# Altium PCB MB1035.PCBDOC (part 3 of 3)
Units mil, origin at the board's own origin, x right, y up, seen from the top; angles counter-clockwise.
Board outline 2598.43 x 3818.9 mil, 2 copper layers (TOP, Bottom); 145 components, 171 nets, 593 pads, 200 vias.
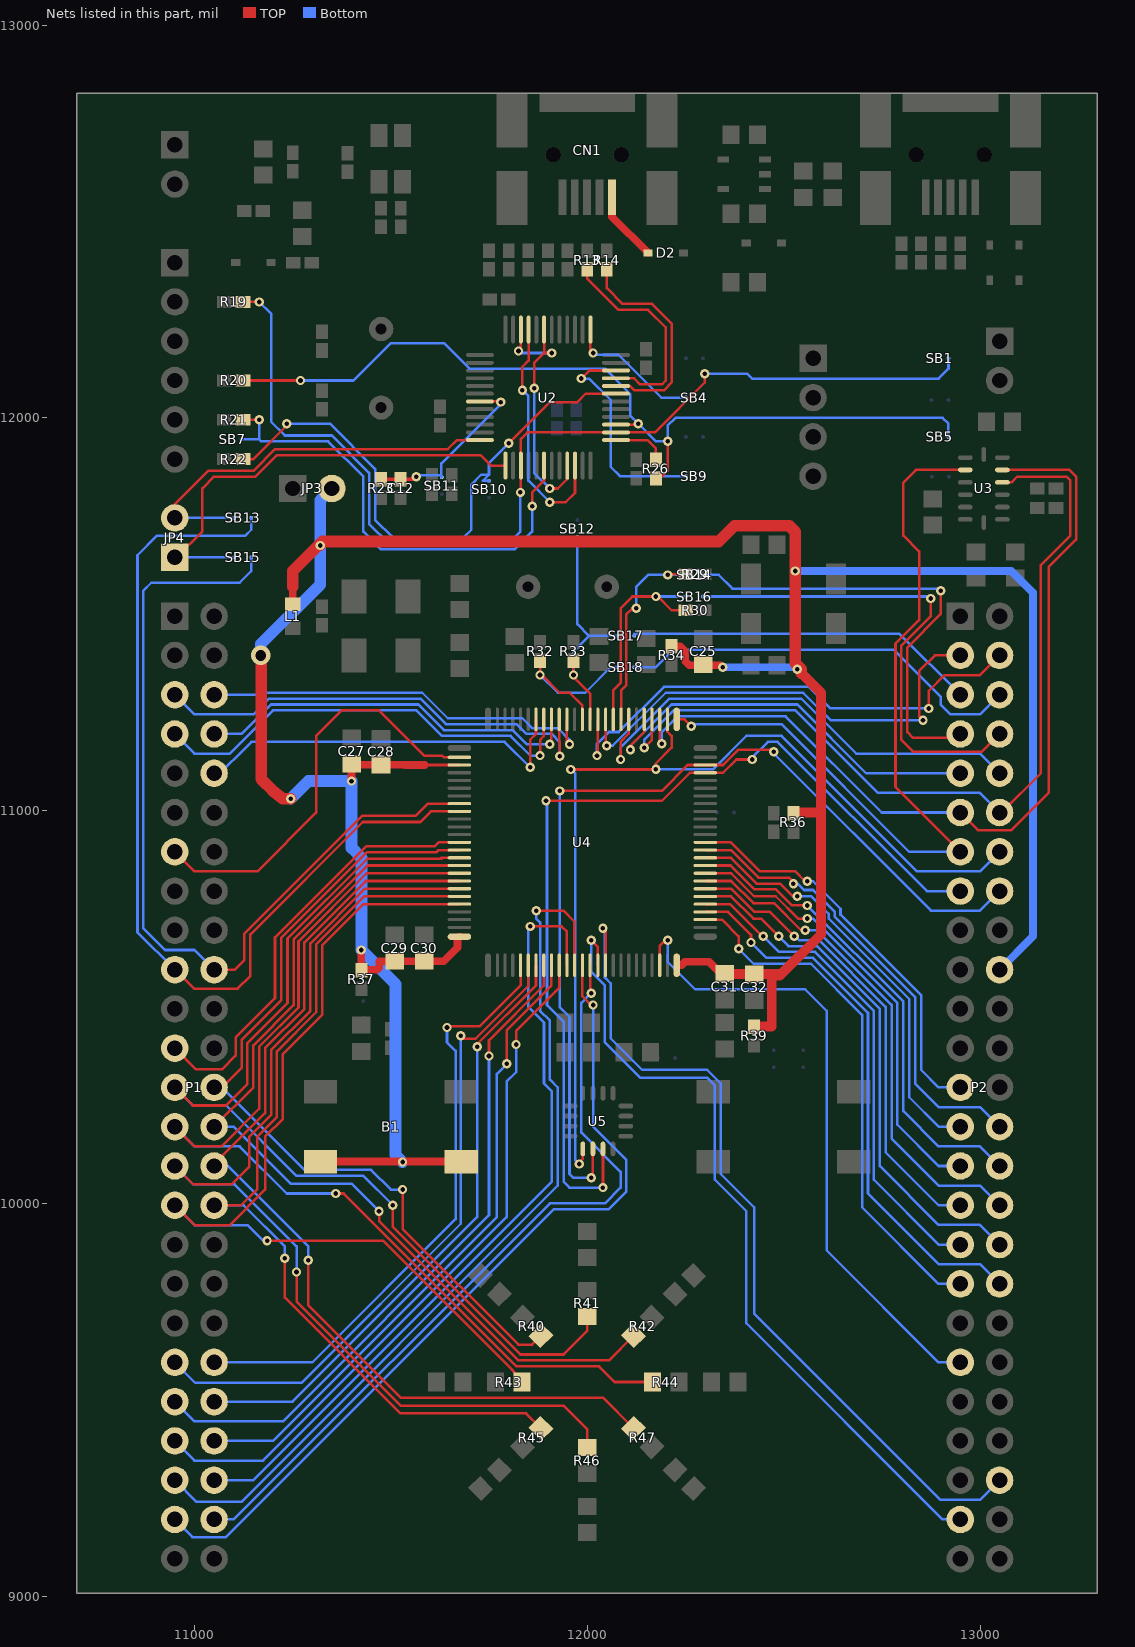
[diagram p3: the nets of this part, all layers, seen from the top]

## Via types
v1: diameter 23.62, hole 11.81, TOP to Bottom, 199 vias
v2: diameter 50, hole 27.56, TOP to Bottom, 1 vias

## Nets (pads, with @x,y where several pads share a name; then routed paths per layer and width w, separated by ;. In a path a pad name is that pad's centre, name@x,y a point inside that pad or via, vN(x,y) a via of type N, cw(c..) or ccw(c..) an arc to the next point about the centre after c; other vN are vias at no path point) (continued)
PC0: P1.6 U4.15 | length 1037.5
  TOP w6.5: U4.15@11947.32,11232.02 11947.32,11168.94 v1(11953.93,11168.94)
  Bottom w6.5: P1.6@11048.93,11294.92 11178.93,11294.92 11183.93,11299.92 11578.93,11299.92 11643.93,11234.92 11833.93,11234.92 11858.93,11209.92 11923.93,11209.92 11953.93,11179.92 v1(11953.93,11168.94)
PC1: P1.5 U4.16 | length 1194.5
  TOP w6.5: U4.16@11927.63,11232.02 11927.63,11176.22 11928.93,11174.92 v1(11928.93,11137.92)
  Bottom w6.5: P1.5@10948.93,11294.92 10998.93,11244.92 11148.93,11244.92 11188.93,11284.92 11573.93,11284.92 11638.93,11219.92 11818.93,11219.92 11843.93,11194.92 11908.93,11194.92 11928.93,11174.92 v1(11928.93,11137.92)
PC2: P1.8 U4.17 | length 1055.2
  TOP w6.5: U4.17@11906.95,11228.47 11906.95,11168.94 v1(11903.93,11168.94) 11907.95,11172.96 U4.17@11907.95,11232.02
  Bottom w6.5: P1.8@11048.93,11194.92 11118.93,11194.92 11193.93,11269.92 11568.93,11269.92 11633.93,11204.92 11808.93,11204.92 11844.92,11168.94 v1(11903.93,11168.94)
PC3: P1.7 U4.18 | length 1139.9
  TOP w6.5: v1(11878.93,11139.92) 11878.93,11179.92 11888.26,11189.25 U4.18@11888.26,11232.02
  Bottom w6.5: P1.7@10948.93,11194.92 10998.93,11144.92 11088.93,11144.92 11198.93,11254.92 11563.93,11254.92 11628.93,11189.92 11803.93,11189.92 11853.93,11139.92 v1(11878.93,11139.92)
PC4: P1.20 SB15.1 U4.33 | length 2253.5
  TOP w6.5: P1.20@11048.93,10594.92 11101.75,10594.93 11125.36,10618.54 11125.36,10686.18 11425.67,10986.48 11562.28,10986.48 11593.25,11017.45 U4.33@11673.69,11017.45
  Bottom w6.5: P1.20@11048.93,10594.92 10998.93,10644.92 10923.93,10644.92 10868.93,10699.92 10868.93,11559.92 10888.93,11579.92 11113.93,11579.92 11143.62,11609.61 SB15.1@11143.62,11644.92
PC5: P1.19 SB13.1 U4.34 | length 2434.6
  TOP w6.5: P1.19@10948.93,10594.92 10998.1,10546.42 11108.93,10546.42 11141.1,10578.59 11141.1,10684.37 11427.47,10970.74 11573.95,10970.74 11601.03,10997.81 11601.07,10997.77 U4.34@11673.69,10997.77
  Bottom w6.5: P1.19@10948.93,10594.92 10853.93,10689.92 10853.93,11649.92 10903.93,11699.92 11128.62,11699.92 11143.62,11714.92 SB13.1@11143.62,11744.92
PC6: P1.47 U4.63 | length 2158.7
  TOP w6.5: U4.63@11986.69,10606.03 11986.69,10527.17 12008.93,10504.92 v1(12013.93,10504.92)
  Bottom w6.5: P1.47@10948.93,9194.92 10993.93,9149.92 11078.93,9149.92 11913.93,9984.92 12053.93,9984.92 12098.93,10029.92 12098.93,10109.92 12013.93,10194.92 v1(12013.93,10504.92)
PC7: P1.48 U4.64 | length 2005.5
  TOP w6.5: U4.64@12006.37,10606.03 12006.37,10534.92 v1(12008.93,10534.92)
  Bottom w6.5: P1.48@11048.93,9194.92 11098.93,9194.92 11903.93,9999.92 12043.93,9999.92 12083.93,10039.92 12083.93,10079.92 11983.93,10179.92 11983.93,10509.92 v1(12008.93,10534.92)
PC8: P2.47 U4.65 | length 2061.3
  TOP w6.5: v1(12008.93,10669.92) 12026.06,10652.8 U4.65@12026.06,10606.03
  Bottom w6.5: v1(12008.93,10669.92) 12008.93,10589.92 12043.93,10554.92 12043.93,10409.92 12133.93,10319.92 12303.93,10319.92 12323.93,10299.92 12323.93,10059.92 12403.93,9979.92 12403.93,9694.92 12903.93,9194.92 P2.47@12948.93,9194.92
PC9: P2.46 U4.66 | length 2179.3
  TOP w6.5: v1(12038.93,10699.92) 12045.74,10699.92 U4.66@12045.74,10606.03
  Bottom w6.5: v1(12038.93,10699.92) 12043.93,10694.92 12043.93,10574.92 12058.93,10559.92 12058.93,10419.92 12138.93,10339.92 12303.93,10339.92 12338.93,10304.92 12338.93,10074.92 12423.93,9989.92 12423.93,9719.92 12898.93,9244.92 12998.93,9244.92 P2.46@13048.93,9294.92
PC10: P2.35 U4.78 | length 1338.7
  TOP w6.5: U4.78@12299.68,10722.18 12341.68,10722.18 12384.56,10679.29 v1(12384.56,10648.07)
  Bottom w6.5: v1(12384.56,10648.07) 12422.71,10609.92 12568.93,10609.92 12698.93,10479.92 12698.93,9989.92 12893.93,9794.92 P2.35@12948.93,9794.92
PC11: P2.36 U4.79 | length 1422.3
  TOP w6.5: U4.79@12299.68,10741.86 12357.4,10741.86 12416.04,10683.22 v1(12416.04,10663.81)
  Bottom w6.5: v1(12416.04,10663.81) 12454.93,10624.92 12573.93,10624.92 12713.93,10484.92 12713.93,10024.92 12893.93,9844.92 12998.93,9844.92 P2.36@13048.93,9794.92
PC12: P2.33 U4.80 | length 1273.2
  TOP w6.5: U4.80@12299.68,10761.55 12362.31,10761.55 12448.93,10674.92 12452.15,10674.92 v1(12447.52,10679.55)
  Bottom w6.5: v1(12447.52,10679.55) 12487.15,10639.92 12578.93,10639.92 12728.93,10489.92 12728.93,10059.92 12893.93,9894.92 P2.33@12948.93,9894.92
PC13: P2.10 U4.7 | length 1236.2
  TOP w6.5: v1(12083.93,11129.92) 12083.93,11174.92 12104.8,11195.79 U4.7@12104.8,11232.02
  Bottom w6.5: v1(12083.93,11129.92) 12083.93,11159.92 12208.93,11284.92 12543.93,11284.92 12683.93,11144.92 12998.93,11144.92 P2.10@13048.93,11094.92
PC14: P2.7 SB14.1 | length 1168.3
  TOP w6.5: v1(12898.93,11559.92) 12898.93,11499.92 12813.93,11414.92 12813.93,11199.92 12828.93,11184.92 12948.93,11184.92 P2.7@12948.93,11194.92
  Bottom w6.5: SB14.1@12293.62,11599.92 12333.93,11599.92 12368.93,11564.92 12893.93,11564.92 v1(12898.93,11559.92)
PC14-OSC32_IN: R29.1 SB14.2 U4.8 | length 546.5
  TOP w6.5: U4.8@12085.11,11232.02 12085.11,11306.1 12098.93,11319.92 12098.93,11499.92 12113.93,11514.92 v1(12123.93,11514.92) ; v1(12203.93,11599.92) 12203.93,11601.42 R29.1@12250.31,11601.42
  Bottom w6.5: v1(12123.93,11514.92) 12123.93,11569.92 12153.93,11599.92 v1(12203.93,11599.92) SB14.2@12250.31,11599.92
PC15: P2.8 SB16.1 | length 1254.5
  TOP w6.5: v1(12873.93,11539.92) 12873.93,11494.92 12798.93,11419.92 12798.93,11179.92 12828.93,11149.92 13003.93,11149.92 P2.8@13048.93,11194.92
  Bottom w6.5: SB16.1@12293.62,11544.92 12863.93,11544.92 12868.93,11539.92 v1(12873.93,11539.92)
PC15-OSC32_OUT: R30.1 SB16.2 U4.9 | length 560.3
  TOP w6.5: U4.9@12065.43,11232.02 12065.43,11306.42 12083.93,11324.92 12083.93,11514.92 12113.93,11544.92 v1(12173.93,11544.92) 12178.93,11544.92 12213.93,11509.92 R30.1@12250.31,11509.92
  Bottom w6.5: v1(12173.93,11544.92) SB16.2@12250.31,11544.92
PD0: P2.34 U4.81 | length 1350.7
  TOP w6.5: U4.81@12299.68,10781.23 12365.27,10781.23 12421.82,10724.68 12441.75,10724.68 v1(12486.87,10679.55)
  Bottom w6.5: v1(12486.87,10679.55) 12511.5,10654.92 12583.93,10654.92 12743.93,10494.92 12743.93,10094.92 12893.93,9944.92 12998.93,9944.92 P2.34@13048.93,9894.92
PD1: P2.31 U4.82 | length 1199.8
  TOP w6.5: U4.82@12299.68,10800.92 12365.27,10800.92 12423.79,10742.39 12463.38,10742.39 v1(12526.22,10679.55)
  Bottom w6.5: v1(12526.22,10679.55) 12528.93,10679.55 12538.56,10669.92 12588.93,10669.92 12758.93,10499.92 12758.93,10129.92 12893.93,9994.92 P2.31@12948.93,9994.92
PD2: P2.32 U4.83 | length 1290.4
  TOP w6.5: U4.83@12299.68,10820.6 12365.27,10820.6 12421.83,10764.04 12474.82,10764.04 12543.93,10694.92 v1(12553.93,10694.92)
  Bottom w6.5: v1(12553.93,10694.92) 12583.93,10694.92 12773.93,10504.92 12773.93,10164.92 12893.93,10044.92 12998.93,10044.92 P2.32@13048.93,9994.92
PD3: P2.29 U4.84 | length 1139.6
  TOP w6.5: U4.84@12299.68,10840.29 12365.27,10840.29 12423.8,10781.75 12479,10781.75 12535.83,10724.92 v1(12558.93,10724.92)
  Bottom w6.5: v1(12558.93,10724.92) 12573.93,10724.92 12788.93,10509.92 12788.93,10199.92 12893.93,10094.92 P2.29@12948.93,10094.92
PD4: P2.30 U4.85 | length 1229.2
  TOP w6.5: U4.85@12299.68,10859.97 12363.89,10859.97 12423.93,10799.92 12478.93,10799.92 12520.6,10758.25 v1(12558.93,10758.25)
  Bottom w6.5: v1(12558.93,10758.25) 12803.93,10513.25 12803.93,10234.92 12893.93,10144.92 12998.93,10144.92 P2.30@13048.93,10094.92
PD5: P2.27 U4.86 | length 1086.3
  TOP w6.5: U4.86@12299.68,10879.66 12365.27,10879.66 12431.68,10813.24 12490.61,10813.24 12521.99,10781.86 v1(12534.09,10781.86)
  Bottom w6.5: v1(12534.09,10781.86) 12568.93,10781.86 12613.93,10736.86 12613.93,10724.92 12818.93,10519.92 12818.93,10269.92 12893.93,10194.92 P2.27@12948.93,10194.92
PD6: P2.28 U4.87 | length 1187.3
  TOP w6.5: U4.87@12299.68,10899.34 12364.52,10899.34 12434.77,10829.08 12513.19,10829.08 12528.93,10813.34 v1(12523.93,10813.34)
  Bottom w6.5: v1(12523.93,10813.34) 12535.51,10813.34 12551.25,10797.6 12573.93,10797.6 12628.93,10742.6 12628.93,10729.92 12833.93,10524.92 12833.93,10304.92 12893.93,10244.92 12998.93,10244.92 P2.28@13048.93,10194.92
PD7: P2.25 U4.88 | length 1027.9
  TOP w6.5: U4.88@12299.68,10919.03 12364.83,10919.03 12438.93,10844.92 12528.93,10844.92 12553.93,10819.92 v1(12558.93,10819.92)
  Bottom w6.5: v1(12558.93,10819.92) 12573.93,10819.92 12643.93,10749.92 12643.93,10734.92 12848.93,10529.92 12848.93,10339.92 12893.93,10294.92 P2.25@12948.93,10294.92
PD8: P1.40 U4.55 | length 1545.9
  TOP w6.5: v1(11641.93,10447.42) 11644.93,10450.42 11725,10450.42 11829.21,10554.63 U4.55@11829.21,10606.03
  Bottom w6.5: P1.40@11048.93,9594.92 11053.93,9594.92 11298.93,9594.92 11663.93,9959.92 11663.93,10387.92 11641.93,10409.92 v1(11641.93,10447.42)
PD9: P1.39 U4.56 | length 1678.9
  TOP w6.5: v1(11676.93,10426.42) 11683.93,10419.42 11715.19,10419.42 11848.89,10553.12 U4.56@11848.89,10606.03
  Bottom w6.5: P1.39@10948.93,9594.92 11000.93,9542.93 11271.94,9542.93 11676.93,9947.92 v1(11676.93,10426.42)
PD10: P1.42 U4.57 | length 1567.8
  TOP w6.5: v1(11718.93,10398.42) 11718.93,10404.92 11868.58,10554.57 U4.57@11868.58,10606.03
  Bottom w6.5: P1.42@11048.93,9494.92 11248.93,9494.92 11718.93,9964.92 v1(11718.93,10398.42)
PD11: P1.41 U4.58 | length 1732
  TOP w6.5: v1(11748.93,10374.92) 11748.93,10414.92 11888.26,10554.25 U4.58@11888.26,10606.03
  Bottom w6.5: P1.41@10948.93,9494.92 10998.93,9444.92 11223.93,9444.92 11748.93,9969.92 v1(11748.93,10374.92)
PD12: P1.44 U4.59 | length 1655.1
  TOP w6.5: v1(11794.31,10354.92) 11793.93,10355.3 11793.93,10439.92 11907.95,10553.94 U4.59@11907.95,10606.03
  Bottom w6.5: P1.44@11048.93,9394.92 11198.93,9394.92 11768.93,9964.92 11768.93,10329.54 v1(11794.31,10354.92)
PD13: P1.43 U4.60 | length 1819
  TOP w6.5: v1(11817.92,10404.1) 11817.92,10438.91 11927.63,10548.62 U4.60@11927.63,10606.03
  Bottom w6.5: P1.43@10948.93,9394.92 10998.93,9344.92 11173.93,9344.92 11793.93,9964.92 11793.93,10309.67 11817.92,10333.66 v1(11817.92,10404.1)
PD14: P1.46 U4.61 | length 2039.1
  TOP w6.5: v1(11853.93,10704.92) 11933.93,10704.92 11947.32,10691.54 U4.61@11947.32,10606.03
  Bottom w6.5: P1.46@11048.93,9294.92 11148.93,9294.92 11908.93,10054.92 11908.93,10284.92 11888.93,10304.92 11888.93,10459.92 11848.93,10499.92 11848.93,10704.92 v1(11853.93,10704.92)
PD15: P1.45 U4.62 | length 2275.1
  TOP w6.5: v1(11868.93,10744.92) 11938.93,10744.92 11966,10717.86 11966,10606.03 U4.62@11967,10606.03
  Bottom w6.5: P1.45@10948.93,9294.92 11003.93,9239.92 11118.93,9239.92 11923.93,10044.92 11923.93,10294.92 11903.93,10314.92 11903.93,10464.92 11878.93,10489.92 11878.93,10714.92 11868.93,10724.92 v1(11868.93,10744.92)
PE0: P2.15 U4.97 U5.7 | length 2472.6
  TOP w6.5: v1(11893.93,11024.92) 12188.93,11024.92 12260.2,11096.19 U4.97@12299.68,11096.19 12345.2,11096.19 12378.93,11129.92 v1(12418.93,11129.92) ; v1(12038.93,10039.92) 12039.14,10039.92 U5.7@12039.14,10138.41
  Bottom w6.5: v1(11893.93,11024.92) 11896.62,11024.92 11896.62,10504.73 11938.93,10462.42 11938.93,10054.92 11953.93,10039.92 v1(12038.93,10039.92) ; v1(12418.93,11129.92) 12418.93,11134.92 12458.93,11174.92 12483.93,11174.92 12863.93,10794.92 P2.15@12948.93,10794.92
PE1: P2.16 U4.98 U5.6 | length 2482.5
  TOP w6.5: v1(11928.93,11049.92) 12188.93,11049.92 12254.89,11115.88 U4.98@12299.68,11115.88 12344.89,11115.88 12383.93,11154.92 12473.93,11154.92 v1(12473.93,11149.92) ; v1(12008.93,10064.92) 12013.55,10064.92 U5.6@12013.55,10138.41
  Bottom w6.5: v1(11928.93,11049.92) 11928.93,10499.92 11953.93,10474.92 11953.93,10074.92 11963.93,10064.92 v1(12008.93,10064.92) ; v1(12473.93,11149.92) 12473.93,11144.92 12873.93,10744.92 12998.93,10744.92 P2.16@13048.93,10794.92
PE2: P2.13 U3.9 U4.1 | length 2096.7
  TOP w6.5: U4.1@12226.84,11232.02 12246.84,11232.02 v1(12263.93,11214.92) ; P2.13@12948.93,10894.92 12783.93,11059.92 12783.93,11424.92 12843.93,11484.92 12843.93,11659.92 12803.93,11699.92 12803.93,11834.92 12836.18,11867.17 U3.9@12961.69,11867.17
  Bottom w6.5: v1(12263.93,11214.92) 12258.93,11219.92 12493.93,11219.92 12818.93,10894.92 P2.13@12948.93,10894.92
PE3: P2.14 U4.2 U5.5 | length 2504.1
  TOP w6.5: v1(11956.93,11104.42) v1@12173.43,11104.42 ; v1(11978.93,10099.92) 11973.93,10099.92 11987.96,10113.95 U5.5@11987.96,10138.41 ; v1(12173.93,11104.92) v1@12173.43,11104.42 ; U4.2@12203.22,11232.02 12203.22,11200.63 12213.93,11189.92 12213.93,11159.92 12173.43,11119.42 v1@12173.43,11104.42
  Bottom w6.5: v1(11956.93,11104.42) 11959.19,11104.42 11968.93,11094.68 11968.93,10109.92 v1(11978.93,10099.92) ; v1(12173.93,11104.92) 12318.93,11104.92 12403.93,11189.92 12493.93,11189.92 12838.93,10844.92 12998.93,10844.92 P2.14@13048.93,10894.92
PE4: P2.11 U3.5 U4.3 | length 2287.4
  TOP w6.5: U4.3@12183.54,11232.02 12183.54,11169.92 v1(12188.93,11169.92) ; P2.11@12948.93,10994.92 12993.93,10949.92 13078.93,10949.92 13173.93,11044.92 13173.93,11619.92 13243.93,11689.92 13243.93,11849.92 13226.69,11867.17 U3.5@13056.18,11867.17
  Bottom w6.5: v1(12188.93,11169.92) 12188.93,11199.92 12228.93,11239.92 12503.93,11239.92 12748.93,10994.92 P2.11@12948.93,10994.92
PE5: P2.12 U3.4 U4.4 | length 2249.4
  TOP w6.5: v1(12143.93,11159.92) 12163.85,11179.84 U4.4@12163.85,11232.02 ; P2.12@13048.93,10994.92 13053.93,10994.92 13153.93,11094.92 13153.93,11624.92 13228.93,11699.92 13228.93,11839.92 13218.93,11849.92 13093.93,11849.92 13079.68,11835.67 U3.4@13056.18,11835.67
  Bottom w6.5: v1(12143.93,11159.92) 12143.93,11179.92 12218.93,11254.92 12528.93,11254.92 12738.93,11044.92 12998.93,11044.92 P2.12@13048.93,10994.92
PE6: P2.9 U4.5 | length 1064.7
  TOP w6.5: v1(12108.93,11154.92) 12103.93,11154.92 12103.93,11159.92 12144.17,11200.16 U4.5@12144.17,11232.02
  Bottom w6.5: v1(12108.93,11154.92) 12108.93,11164.92 12213.93,11269.92 12533.93,11269.92 12708.93,11094.92 P2.9@12948.93,11094.92
PE7: P1.23 U4.38 | length 1104.1
  TOP w6.5: P1.23@10948.93,10394.92 11002.71,10341.14 11068.93,10341.14 11103.93,10376.14 11103.93,10422.29 11204.06,10522.42 11204.06,10677.16 11435.83,10908.92 11610.69,10908.92 11620.79,10919.03 U4.38@11673.69,10919.03
PE8: P1.26 R40.2 U4.39 | length 2181.1
  TOP w6.5: P1.26@11048.93,10294.92 11068.93,10294.92 11118.93,10344.92 11118.93,10415.55 11219.8,10516.42 11219.8,10675.35 11438.37,10893.92 11615.18,10893.92 11620.6,10899.34 U4.39@11673.69,10899.34 ; v1(11528.93,10034.92) 11528.93,9934.92 11823.93,9639.92 11858.42,9639.92 R40.2@11881.18,9662.68
  Bottom w6.5: P1.26@11048.93,10294.92 11068.93,10294.92 11278.93,10084.92 11448.93,10084.92 11498.93,10034.92 v1(11528.93,10034.92)
PE9: P1.25 R41.2 U4.40 | length 2588.9
  TOP w6.5: P1.25@10948.93,10294.92 10994.93,10248.92 11078.93,10248.92 11133.93,10303.92 11133.93,10407.92 11235.93,10509.92 11235.93,10673.94 11438.92,10876.92 11627.93,10876.92 11627.93,10879.66 U4.40@11673.69,10879.66 ; v1(11503.93,9994.92) 11503.93,9939.92 11828.93,9614.92 11938.93,9614.92 11998.93,9674.92 R41.2@11998.93,9711.46
  Bottom w6.5: P1.25@10948.93,10294.92 10994.93,10248.92 11079.93,10248.92 11258.93,10069.92 11428.93,10069.92 v1(11503.93,9994.92)
PE10: P1.28 R42.2 U4.41 | length 2415.9
  TOP w6.5: P1.28@11048.93,10194.92 11148.93,10294.92 11148.93,10402.07 11251.28,10504.42 11251.28,10671.74 11439.51,10859.97 U4.41@11673.69,10859.97 ; v1(11468.93,9979.92) 11468.93,9954.92 11823.93,9599.92 12053.93,9599.92 R42.2@12116.69,9662.68
  Bottom w6.5: P1.28@11048.93,10194.92 11098.93,10194.92 11243.93,10049.92 11398.93,10049.92 v1(11468.93,9979.92)
PE11: P1.27 R44.2 U4.42 | length 2710.2
  TOP w6.5: P1.27@10948.93,10194.92 10998.93,10144.92 11067.93,10144.92 11163.93,10240.92 11163.93,10398.92 11263.93,10498.92 11263.93,10666.85 11437.37,10840.29 U4.42@11673.69,10840.29 ; v1(11358.93,10024.92) 11378.93,10024.92 11818.93,9584.92 12028.93,9584.92 12068.93,9544.92 R44.2@12165.47,9544.92
  Bottom w6.5: P1.27@10948.93,10194.92 10998.93,10144.92 11113.93,10144.92 11233.93,10024.92 v1(11358.93,10024.92)
PE12: P1.30 R47.2 U4.43 | length 2556.4
  TOP w6.5: P1.30@11048.93,10094.92 11048.93,10099.92 11178.93,10229.92 11178.93,10394.92 11278.93,10494.92 11278.93,10664.31 11435.23,10820.6 U4.43@11673.69,10820.6 ; v1(11288.93,9854.92) 11288.93,9739.92 11523.93,9504.92 12038.93,9504.92 R47.2@12116.69,9427.16
  Bottom w6.5: P1.30@11048.93,10094.92 11083.93,10094.92 11288.93,9889.92 v1(11288.93,9854.92)
PE13: P1.29 R46.2 U4.44 | length 2754
  TOP w6.5: P1.29@10948.93,10094.92 10995.93,10047.92 11092.93,10047.92 11137.93,10092.92 11137.93,10168.92 11193.93,10224.92 11193.93,10389.92 11293.93,10489.92 11293.93,10661.76 11433.09,10800.92 U4.44@11673.69,10800.92 ; v1(11258.93,9824.92) 11258.93,9749.92 11523.93,9484.92 11938.93,9484.92 11998.93,9424.92 R46.2@11998.93,9378.39
  Bottom w6.5: P1.29@10948.93,10094.92 10995.93,10047.92 11100.93,10047.92 11258.93,9889.92 v1(11258.93,9824.92)
PE14: P1.32 R45.2 U4.45 | length 2371
  TOP w6.5: P1.32@11048.93,9994.92 11088.93,9994.92 11117.49,9994.93 11158.93,10036.37 11158.93,10169.92 11208.93,10219.92 11208.93,10386.42 11308.93,10486.42 11308.93,10659.22 11430.95,10781.23 U4.45@11673.69,10781.23 ; v1(11228.93,9859.92) 11228.93,9759.92 11523.93,9464.92 11843.42,9464.92 R45.2@11881.18,9427.16
  Bottom w6.5: P1.32@11048.93,9994.92 11123.93,9994.92 11228.93,9889.92 v1(11228.93,9859.92)
PE15: P1.31 R43.2 U4.46 | length 2435.9
  TOP w6.5: P1.31@10948.93,9994.92 10999.93,9943.92 11087.93,9943.92 11178.93,10034.92 11178.93,10169.92 11223.93,10214.92 11223.93,10379.92 11323.93,10479.92 11323.93,10656.67 11428.81,10761.55 U4.46@11673.69,10761.55 ; v1(11183.93,9904.92) 11478.93,9904.92 11807.4,9576.46 R43.2@11832.4,9544.92
  Bottom w6.5: P1.31@10948.93,9994.92 10999.93,9943.92 11134.93,9943.92 11173.93,9904.92 v1(11183.93,9904.92)
PF0: P2.5 SB17.1 | length 899.5
  Bottom w6.5: SB17.1@12118.62,11444.92 12118.62,11449.92 12793.93,11449.92 P2.5@12948.93,11294.92
PF0-OSC_IN: R33.1 SB12.2 SB17.2 U4.12 | length 618.6
  TOP w6.5: R33.1@11963.93,11381.3 v1(11963.93,11344.92) 11963.93,11339.92 12006.37,11297.48 U4.12@12006.37,11232.02
  Bottom w6.5: v1(11963.93,11344.92) 11963.93,11404.92 12003.93,11444.92 ; SB12.2@11973.93,11696.3 11973.93,11474.92 12003.93,11444.92 ; SB17.2@12075.31,11444.92 12003.93,11444.92
PF1: P2.6 SB18.1 | length 1049.7
  Bottom w6.5: SB18.1@12118.62,11364.92 12173.93,11364.92 12218.93,11409.92 12778.93,11409.92 12898.93,11289.92 12898.93,11269.92 12923.93,11244.92 12998.93,11244.92 P2.6@13048.93,11294.92
PF1-OSC_OUT: R32.1 SB18.2 U4.13 | length 453.4
  TOP w6.5: R32.1@11878.93,11381.3 v1(11878.93,11344.92) 11883.93,11344.92 11928.93,11299.92 11953.93,11299.92 11986.69,11267.17 U4.13@11986.69,11232.02
  Bottom w6.5: v1(11878.93,11344.92) 11923.93,11299.92 11993.93,11299.92 12058.93,11364.92 SB18.2@12075.31,11364.92
PF2: P1.10 U4.19 | length 1035.6
  TOP w6.5: v1(11853.93,11109.92) 11853.93,11180.28 11868.58,11194.92 U4.19@11868.58,11232.02
  Bottom w6.5: P1.10@11048.93,11094.92 11033.93,11079.92 11048.93,11079.92 11143.93,11174.92 11788.93,11174.92 v1(11853.93,11109.92)
PF4: P1.13 U4.27 | length 1079
  TOP w6.5: P1.13@10948.93,10894.92 10998.93,10844.92 11158.93,10844.92 11308.93,10994.92 11308.93,11189.92 11373.93,11254.92 11468.93,11254.92 11583.93,11139.92 11629.57,11139.92 11633.93,11135.56 U4.27@11673.69,11135.56
PF6: P2.39 U4.73 | length 1662.2
  TOP w6.5: U4.73@12183.54,10606.03 12183.54,10654.53 12203.93,10674.92 v1(12203.93,10669.92)
  Bottom w6.5: v1(12203.93,10669.92) 12203.93,10614.92 12273.93,10544.92 12553.93,10544.92 12608.93,10489.92 12608.93,9879.92 12893.93,9594.92 P2.39@12948.93,9594.92
PF9: P2.3 U4.10 | length 1209
  TOP w6.5: U4.10@12045.74,11232.02 12045.74,11168.11 v1(12048.93,11164.92) ; v1(12853.93,11229.92) 12843.93,11239.92 12843.93,11354.92 12883.93,11394.92 P2.3@12948.93,11394.92
  Bottom w6.5: v1(12048.93,11164.92) 12063.93,11164.92 12198.93,11299.92 12548.93,11299.92 12618.93,11229.92 v1(12853.93,11229.92)
PF10: P2.4 U4.11 | length 1314.3
  TOP w6.5: v1(12023.93,11139.92) 12026.06,11139.92 U4.11@12026.06,11232.02 ; v1(12868.93,11259.92) 12868.93,11304.92 12908.93,11344.92 12998.93,11344.92 P2.4@13048.93,11394.92
  Bottom w6.5: v1(12023.93,11139.92) 12023.93,11169.92 12053.93,11199.92 12078.93,11199.92 12193.93,11314.92 12563.93,11314.92 12618.93,11259.92 v1(12868.93,11259.92)
STLINK_RX: JP4.1 SB15.2 U2.13 | length 1176.3
  TOP w6.5: JP4.1@10948.93,11644.92 10953.93,11644.92 11018.93,11709.92 11018.93,11819.92 11048.93,11849.92 11153.93,11849.92 11208.93,11904.92 11727.21,11904.92 11753.93,11878.19 U2.13@11790.67,11878.19
  Bottom w6.5: JP4.1@10948.93,11644.92 SB15.2@11100.31,11644.92
STLINK_TX: JP4.2 SB13.2 U2.12 | length 1030.8
  TOP w6.5: JP4.2@10948.93,11744.92 10948.93,11779.92 11033.93,11864.92 11148.93,11864.92 11203.93,11919.92 11643.93,11919.92 11667.16,11943.15 U2.12@11725.71,11943.15
  Bottom w6.5: JP4.2@10948.93,11744.92 SB13.2@11100.31,11744.92
STM_JTCK: SB4.2 U2.37 | length 352.5
  TOP w6.5: U2.37@12007.2,12224.65 12007.2,12164.92 v1(12013.93,12164.92)
  Bottom w6.5: v1(12013.93,12164.92) 12013.93,12160.42 12078.44,12160.42 12187.43,12051.42 SB4.2@12250.31,12051.42
STM_JTMS: SB9.2 U2.34 | length 565.6
  TOP w6.5: v1(11983.93,12099.92) 12004.33,12120.32 U2.34@12072.16,12120.32
  Bottom w6.5: v1(11983.93,12099.92) 12003.93,12099.92 12058.93,12044.92 12058.93,11874.92 12082.43,11851.42 SB9.2@12250.31,11851.42
STM_RST: C12.2 R23.1 SB11.2 U2.7 | length 473.2
  TOP w6.5: U2.7@11725.71,12041.58 11778.93,12041.58 v1(11778.93,12039.92)
  TOP w9.84: R23.1@11473.93,11843.54 C12.2@11523.93,11843.54 11563.93,11843.54 v1(11563.93,11849.92)
  Bottom w6.5: v1(11563.93,11849.92) 11563.93,11853.54 11627.56,11853.54 ; SB11.2@11628.93,11848.54 11627.56,11849.92 11627.56,11853.54 ; v1(11778.93,12039.92) 11778.93,12034.92 11627.56,11883.54 11627.56,11853.54
SWIM: U2.22 U2.45 | length 618.4
  TOP w6.5: v1(11833.93,12069.92) 11833.93,12129.92 11849.72,12145.71 U2.45@11849.72,12224.65 ; v1(11903.93,11784.92) 11943.93,11784.92 11967.83,11808.82 U2.22@11967.83,11878.19
  Bottom w6.5: v1(11833.93,12069.92) 11848.93,12054.92 11848.93,11839.92 v1(11903.93,11784.92)
SWIM_IN: U2.21 U2.43 U2.46 | length 687.1
  TOP w6.5: v1(11823.93,12169.92) 11830.04,12176.03 U2.46@11830.04,12224.65 ; v1(11863.93,12074.92) 11863.93,12139.77 11889.09,12164.92 ; U2.43@11889.09,12224.65 11889.09,12164.92 ; v1(11903.93,11819.92) 11923.93,11819.92 11948.15,11844.14 U2.21@11948.15,11878.19 ; v1(11908.93,12164.92) 11889.09,12164.92
  Bottom w6.5: v1(11823.93,12169.92) 11823.93,12164.92 v1(11908.93,12164.92) ; v1(11863.93,12074.92) 11863.93,11859.92 v1(11903.93,11819.92)
T_JTCK: R19.2 SB1.1 U2.15 U2.26 | length 2662.8
  TOP w6.5: R19.2@11122.56,12294.92 v1(11163.93,12294.92) ; v1(11828.93,11809.92) 11830.04,11809.92 U2.15@11830.04,11879.92 ; U2.15@11830.04,11878.19 U2.15@11830.04,11879.92 ; v1(12298.15,12111.89) 12298.15,12089.14 12171.85,11962.84 U2.26@12072.16,11962.84 11846.85,11962.84 11830.04,11946.03 U2.15@11830.04,11879.92
  Bottom w6.5: v1(11163.93,12294.92) 11193.93,12264.92 11193.93,11989.92 11228.93,11954.92 11348.93,11954.92 11443.93,11859.92 11443.93,11729.92 11493.93,11679.92 11798.93,11679.92 11828.93,11709.92 v1(11828.93,11809.92) ; v1(12298.15,12111.89) 12406.96,12111.89 12418.93,12099.92 12893.93,12099.92 12918.93,12124.92 12918.93,12151.42 SB1.1@12918.62,12151.42
T_JTMS: R20.2 R26.2 SB5.1 U2.27 | length 2242.9
  TOP w6.5: R20.2@11122.56,12094.92 v1(11268.93,12094.92) ; U2.27@12072.16,11982.53 12128.93,11982.53 12132.63,11986.22 12133.93,11984.92 v1(12128.93,11984.92) ; R26.2@12173.93,11846.3 12173.93,11849.92 12188.93,11849.92 12203.93,11864.92 v1(12203.93,11939.92)
  Bottom w6.5: v1(11268.93,12094.92) 11403.93,12094.92 11498.93,12189.92 11633.93,12189.92 11698.93,12124.92 12043.93,12124.92 12108.93,12059.92 12108.93,12004.92 v1(12128.93,11984.92) 12173.93,11939.92 v1(12203.93,11939.92) 12203.93,11979.92 12223.93,11999.92 12903.62,11999.92 12918.62,11984.92 SB5.1@12918.62,11951.42
T_NRST: R21.2 SB7.1 U2.18 | length 1229.1
  TOP w6.5: R21.2@11122.56,11994.92 v1(11163.93,11994.92) ; v1(11858.93,11774.92) 11858.93,11809.92 11889.09,11840.08 U2.18@11889.09,11878.19
  Bottom w6.5: SB7.1@11118.62,11944.92 11163.93,11944.92 ; v1(11163.93,11994.92) 11163.93,11944.92 ; v1(11858.93,11774.92) 11858.93,11709.92 11813.93,11664.92 11473.93,11664.92 11428.93,11709.92 11428.93,11849.92 11338.93,11939.92 11168.93,11939.92 11163.93,11944.92
T_SWDIO_IN: R26.1 U2.25 | length 138.5
  TOP w6.5: U2.25@12072.16,11943.16 12151.98,11943.16 12173.93,11921.2 R26.1@12173.93,11893.54
T_SWO: R22.2 SB10.1 U2.31 | length 1459.7
  TOP w6.5: R22.2@11122.56,11894.92 11148.93,11894.92 11233.93,11979.92 v1(11233.93,11984.92) ; v1(11798.93,11934.92) 11903.93,12039.92 11973.93,12039.92 11995.28,12061.27 U2.31@12072.16,12061.27
  Bottom w6.5: v1(11233.93,11984.92) 11343.93,11984.92 11458.93,11869.92 11458.93,11739.92 11503.93,11694.92 11683.93,11694.92 11703.93,11714.92 11703.93,11829.92 11728.93,11854.92 11748.93,11854.92 ; SB10.1@11748.93,11839.61 11733.62,11839.61 11748.93,11854.92 ; v1(11798.93,11934.92) 11748.93,11884.92 11748.93,11854.92
U5V: CN1.1 D2.1 | length 179.9
  TOP w19.68: CN1.1@12061.82,12561.66 12061.82,12512.04 D2.1@12153.93,12419.92
USB_DM: R14.2 U2.32 | length 554.8
  TOP w6.5: R14.2@12048.93,12377.8 12048.93,12329.92 12088.93,12289.92 12163.93,12289.92 12213.93,12239.92 12213.93,12089.92 12193.93,12069.92 12118.93,12069.92 12107.91,12080.95 U2.32@12072.16,12080.95
USB_DP: R13.2 U2.33 | length 547.1
  TOP w6.5: R13.2@11998.93,12377.8 11998.93,12354.92 12078.93,12274.92 12153.93,12274.92 12198.93,12229.92 12198.93,12094.92 12188.93,12084.92 12133.93,12084.92 12118.22,12100.64 U2.33@12072.16,12100.64
VDD: B1.1 B1.2 C25.2 C27.2 C28.2 C29.2 C30.2 C31.1 C32.1 JP3.2 L1.1 P2.20 R34.2 R36.1 R37.2 R39.2 U4.28 U4.50 U4.75 | length 8359.3
  TOP w6.5: 11585.38,11115.88 U4.28@11673.69,11115.88
  TOP w9.84: U4.75@12226.84,10606.03 12238.93,10606.03
  TOP w19.68: L1.1@11248.93,11524.92 11248.93,11569.92 ; B1.2@11319.8,10106.34 v1@11528.93,10106.34 ; C27.2@11398.93,11116.46 C28.2@11473.93,11116.46 ; R37.2@11423.93,10593.54 R37.2@11423.93,10594.92 ; v1(11423.93,10644.92) R37.2@11423.93,10594.92 ; v1(11528.93,10104.92) v1@11528.93,10106.34 ; U4.50@11673.69,10678.87 11668.93,10674.11 11668.93,10651.46 11633.93,10616.46 C30.2@11583.93,10616.46 C29.2@11508.93,10616.46 11469.56,10616.46 11469.56,10600.55 11463.93,10594.92 R37.2@11423.93,10594.92 ; B1.1@11678.07,10106.34 v1@11528.93,10106.34 ; R34.2@12213.93,11418.54 12235.31,11418.54 12248.93,11404.92 12248.93,11379.92 12258.93,11369.92 C25.2@12295.47,11369.92 ; 12238.93,10606.03 12247.82,10614.92 12308.93,10614.92 12338.97,10584.89 12343.93,10584.89 C31.1@12348.93,10584.89 ; C25.2@12293.93,11371.46 C25.2@12295.47,11369.92 ; v1(12343.93,11364.92) 12338.93,11369.92 C25.2@12295.47,11369.92
  TOP w20: v1(11398.93,11074.92) 11398.93,11116.46 C27.2@11398.93,11117.96 ; C28.2@11473.93,11116.46 11535.47,11116.46 11534.89,11115.88 11585.38,11115.88
  TOP w25: C31.1@12343.93,10584.89 12345.43,10583.39 C32.1@12423.93,10583.39 12488.93,10583.39 12488.93,10579.3 ; R39.2@12423.93,10450.04 12468.93,10450.04 12468.93,10579.3 12488.93,10579.3 ; R36.1@12523.93,10993.54 12525.31,10994.92 12593.93,10994.92 ; v1(12533.93,11359.92) v1@12543.93,11359.92 ; 12543.93,11349.92 12593.93,11299.92 12593.93,10994.92 ; 12488.93,10579.3 12593.93,10684.3 12593.93,10994.92
  TOP w29.53: 11248.93,11569.92 11248.93,11609.92 v1@11318.93,11679.92 ; v1(11318.93,11674.92) v1@11318.93,11679.92 ; 12518.93,11719.92 12513.93,11724.92 12373.93,11724.92 12333.93,11684.92 11323.93,11684.92 v1@11318.93,11679.92
  TOP w30: v2(11167.93,11394.93) 11168.93,11393.93 11168.93,11079.92 11198.93,11049.92 11223.93,11029.92 v1(11243.93,11029.92) ; 12518.93,11719.92 12528.93,11709.92 v1(12528.93,11609.92) 12528.93,11374.92 12543.93,11359.92 12543.93,11349.92
  Bottom w19.68: v1(12343.93,11364.92) 12533.93,11364.92 v1(12533.93,11359.92) ; v1(12528.93,11609.92) 13078.93,11609.92 13133.93,11554.92 13133.93,10679.92 P2.20@13048.93,10594.92
  Bottom w29.53: v2(11167.93,11394.93) 11167.93,11423.92 11318.93,11574.92 11318.93,11634.92 ; v1(11318.93,11674.92) 11318.93,11634.92 ; JP3.2@11348.93,11819.92 11318.93,11789.92 11318.93,11634.92
  Bottom w30: v1(11243.93,11029.92) 11288.93,11074.92 v1(11398.93,11074.92) 11398.93,10904.92 11423.93,10879.92 v1(11423.93,10644.92) 11510.99,10557.86 11510.99,10122.86 v1(11528.93,10104.92)
pads on no net: CN1.11 CN1.12 CN2.11 CN2.12 P2.48 U2.4 U2.11 U2.14 U2.16 U2.17 U2.19 U2.28 U2.38 U2.39 U2.40 U2.41 U2.42 U3.8 X3.2 X3.3

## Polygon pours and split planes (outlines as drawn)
GND on Bottom "Template_3" (solid, remove dead copper): 10498.93,8894.92 13593.93,8894.92 13593.93,13139.92 10498.93,13139.92
GND on TOP "Template_2" (solid, remove dead copper): 10493.93,8909.92 13588.93,8909.92 13588.93,13154.92 10493.93,13154.92

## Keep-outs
Keep-Out Layer:
  the board outline again, w10

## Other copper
TOP:
  text "FACE 1" at 9948.93,5369.92 h96.46
Bottom:
  text "FACE 2" at 9943.93,5389.92 h96.46

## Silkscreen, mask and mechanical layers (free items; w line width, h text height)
Top Silk:
  drawing of 309 lines, arcs and shapes, not listed
  text "COM" at 11633.93,12599.92 h59.06 r90
  text "GND" at 10873.93,12594.92 h59.06 r90
  text "PWR" at 11133.93,12594.92 h59.06 r90
  text "USB USER" at 13236.93,12536.92 h59.06 r90
  text "USB ST-LINK" at 11744.93,12506.92 h59.06 r90
  text "GND" at 12973.93,12094.92 h59.06 r90
  text "SWD" at 10865.08,12090.2 h59.06 r90
  text "ST-LINK" at 12418.93,11936.92 h59.06 r90
  text "DISCOVERY" at 12789.93,11893.92 h59.06 r90
  text "ldd" at 11248.93,11869.92 h59.06
  text "TX" at 10748.93,11715.4 h59.06
  text "www.st.com/stm32f3discovery" at 11022.93,11662.92 h98.43
  text "RX" at 10748.93,11615.4 h59.06
  text "5V" at 13128.55,11467.1 h59.06
  text "3V" at 10748.93,11465.4 h59.06
  text "5V" at 12748.93,11465.4 h59.06
  text "3V" at 11108.93,11460.4 h59.06
  text "PF10" at 13128.15,11367.5 h59.06
  text "GND" at 10748.93,11365.4 h59.06
  text "PF9" at 12748.93,11365.4 h59.06
  text "NRST" at 11108.93,11360.4 h59.06
  text "PF1" at 13129.13,11267.3 h59.06
  text "PC1" at 10748.93,11265.4 h59.06
  text "PF0" at 12748.93,11265.4 h59.06
  text "PC0" at 11108.93,11260.4 h59.06
  text "PC3" at 10748.93,11165.4 h59.06
  text "PC14" at 12748.93,11165.4 h59.06
  text "PC15" at 13123.93,11165.4 h59.06
  text "PC2" at 11108.93,11160.4 h59.06
  text "PA1" at 10748.93,11065.4 h59.06
  text "PE6" at 12748.93,11065.4 h59.06
  text "PC13" at 13123.93,11065.4 h59.06
  text "PF2" at 11108.93,11060.4 h59.06
  text "PA3" at 10748.93,10965.4 h59.06
  text "PE4" at 12748.93,10965.4 h59.06
  text "PE5" at 13123.93,10965 h59.06
  text "PA0" at 11108.93,10960.4 h59.06
  text "PF4" at 10748.93,10865.4 h59.06
  text "PE2" at 12748.93,10865.4 h59.06
  text "PE3" at 13123.93,10865.4 h59.06
  text "PA2" at 11108.93,10860.4 h59.06
  text "PA5" at 10748.93,10765.4 h59.06
  text "PE0" at 12748.93,10765.4 h59.06
  text "PE1" at 13123.93,10765.2 h59.06
  text "PA4" at 11108.93,10760.4 h59.06
  text "MB1035B" at 12348.93,10736.92 h86.61
  text "PA7" at 10748.93,10665.4 h59.06
  text "PB8" at 12748.93,10665.4 h59.06
  text "PB9" at 13123.93,10665.4 h59.06
  text "PA6" at 11108.93,10660.4 h59.06
  text "PC5" at 10748.93,10565.4 h59.06
  text "BOOT0" at 12673.93,10565.4 h59.06
  text "VDD" at 13119.73,10563.8 h59.06
  text "PC4" at 11108.93,10560.4 h59.06
  text "PB1" at 10748.93,10465.4 h59.06
  text "PB6" at 12748.93,10465.4 h59.06
  text "PB7" at 13123.93,10465 h59.06
  text "PB0" at 11108.93,10460.4 h59.06
  text "PE7" at 10748.93,10365.4 h59.06
  text "PB4" at 12748.93,10365.4 h59.06
  text "PB5" at 13123.93,10365 h59.06
  text "PB2" at 11108.93,10360.4 h59.06
  text "PE9" at 10748.93,10265.4 h59.06
  text "PD7" at 12748.93,10265.4 h59.06
  text "PB3" at 13123.93,10265.4 h59.06
  text "PE8" at 11108.93,10260.4 h59.06
  text "PE11" at 10748.93,10165.4 h59.06
  text "PD5" at 12748.93,10165.4 h59.06
  text "PD6" at 13123.93,10165.4 h59.06
  text "PE10" at 11108.93,10160.4 h59.06
  text "PE13" at 10748.93,10065.4 h59.06
  text "PD3" at 12748.93,10065.4 h59.06
  text "PD4" at 13123.93,10065 h59.06
  text "PE12" at 11108.93,10060.4 h59.06
  text "RESET" at 12419.93,9982.92 h59.06
  text "USER" at 11408.93,9974.92 h59.06
  text "PE15" at 10748.93,9965.4 h59.06
  text "PD1" at 12748.93,9965.4 h59.06
  text "PD2" at 13123.93,9965.4 h59.06
  text "PE14" at 11108.93,9960.4 h59.06
  text "N" at 11969.09,9945.71 h98.43
  text "PB11" at 10748.93,9865.4 h59.06
  text "PC12" at 12748.93,9865.4 h59.06
  text "PD0" at 13123.93,9865.4 h59.06
  text "PB10" at 11108.93,9860.4 h59.06
  text "PB13" at 10748.93,9765.4 h59.06
  text "PC10" at 12748.93,9765.4 h59.06
  text "PC11" at 13123.93,9765.2 h59.06
  text "PB12" at 11108.93,9760.4 h59.06
  text "PB15" at 10748.93,9665.4 h59.06
  text "PA14" at 12748.93,9665.4 h59.06
  text "PA15" at 13123.93,9665.2 h59.06
  text "PB14" at 11108.93,9660.4 h59.06
  text "PD9" at 10748.93,9565.4 h59.06
  text "PF6" at 12748.93,9565.4 h59.06
  text "PA13" at 13123.93,9565.4 h59.06
  text "PD8" at 11108.93,9560.4 h59.06
  text "E" at 12434.39,9471.71 h98.43
  text "W" at 11478.38,9470.71 h98.43
  text "PD11" at 10748.93,9465.4 h59.06
  text "PA12" at 12748.93,9465.4 h59.06
  text "PA11" at 13123.93,9465.4 h59.06
  text "PD10" at 11108.93,9460.4 h59.06
  text "PD13" at 10748.93,9365.4 h59.06
  text "PA10" at 12748.93,9365.4 h59.06
  text "PA9" at 13123.93,9365.4 h59.06
  text "PD12" at 11108.93,9360.4 h59.06
  text "PD15" at 10748.93,9265.4 h59.06
  text "PA8" at 12748.93,9265.4 h59.06
  text "PC9" at 13123.93,9265.4 h59.06
  text "PD14" at 11108.93,9260.4 h59.06
  text "PC6" at 10748.93,9165.4 h59.06
  text "PC8" at 12748.93,9165.4 h59.06
  text "PC7" at 11108.93,9160.4 h59.06
  text "NC" at 13123.93,9160.4 h59.06
  text "GND" at 10748.93,9065.4 h59.06
  text "GND" at 12748.93,9065.4 h59.06
  text "GND" at 13123.93,9065.4 h59.06
  text "GND" at 11108.93,9060.4 h59.06
  text "S" at 11968.85,9011.71 h98.43
  text "SERIGRAPHIE FACE 1" at 9948.93,5369.92 h96.46
Bot Silk:
  lines w7.87: 11252.79,9111.85 11252.79,9348.07 12040.19,9348.07 12040.19,9111.85 11252.79,9111.85 ; 12224.26,9209.29 cw(c12337.67,9209.29) 12451.08,9209.29 cw(c12337.67,9209.29) 12224.26,9209.29
  lines w8: 12208.93,11814.92 12208.93,12189.92 12338.93,12189.92 12338.93,11814.92 12208.93,11814.92 ; 12833.93,11814.92 12833.93,12189.92 12963.93,12189.92 12963.93,11814.92 12833.93,11814.92
  text "DEFAULT" at 12748.93,11926.57 h59.06 r270
  text "RESERVED" at 12353.93,11902.99 h59.06 r270
  text "SN" at 11626.62,9199.92 h41.34
  text "RoHS" at 12391.27,9175.92 h41.34
  text "SERIGRAPHIE FACE 2" at 9928.93,5394.92 h96.46
Top Paste:
  text "MASQUE DE BRASAGE FACE 1" at 9898.93,5344.92 h96.46
Top Mask:
  text "VERNIS EPARGNE FACE 1" at 9953.93,5389.92 h96.46
Bot Mask:
  text "VERNIS EPARGNE FACE 2" at 9958.93,5384.92 h96.46
User Attributes:
  lines w10: 11623.93,9549.92 11973.93,9549.92 ; 11726.45,9302.44 11973.93,9549.92 ; 11726.45,9797.41 11973.93,9549.92 ; 12221.42,9302.44 11973.93,9549.92 ; 12221.42,9797.41 11973.93,9549.92 ; 12323.93,9549.92 11973.93,9549.92 ; 11973.93,9199.92 ccw(c11973.93,9549.92) 11973.93,9899.92 ; 11973.93,9199.92 cw(c11973.93,9549.92) 11973.93,9899.92 ; 11973.93,9199.92 11973.93,9549.92 ; 11973.93,9549.92 11973.93,9899.92 ; 11973.93,9349.92 ccw(c11973.93,9549.92) 11973.93,9749.92 ccw(c11973.93,9549.92) 11973.93,9349.92
PERCAGES:
  text "PLAN DE PERCAGES" at 9948.93,5394.92 h96.46
  text "PLAN DE PERCAGES" at 9915.93,5368.92 h70
CARTOUCHE F1:
  region: 14698.93,4844.92 14928.48,4845.03 14938.93,4865.92 14848.93,4955.92 14836.93,4982.92 14836.93,5015.92 14839.93,5027.92 14851.93,5048.92 14863.93,5060.92 14878.93,5069.92 14896.93,5075.92 14917.93,5078.92 15343.93,5078.92 15319.93,5015.92 15316.93,5012.92 15217.93,5012.92 15121.93,4784.92 15052.93,4784.92 15145.93,5003.92 15145.93,5012.92 14908.93,5012.92 14902.93,5009.92 14899.93,5003.92 14899.93,4994.92 14902.93,4991.92 14989.93,4907.92 14998.93,4892.92 15001.93,4877.92 15004.93,4874.92 15004.93,4847.92 cw(c14915.45,4866.32) 14956.93,4784.92 14674.93,4784.92 14674.93,4790.92 14695.93,4841.92
  lines w8: 9861.4,4473.85 14161.4,4473.85 ; 9861.4,4823.85 14161.4,4823.85 ; 14674.93,4784.92 14674.93,4790.92 14794.93,5081.92 cw(c14880.37,5039.57) 14860.93,5132.92 15358.93,5132.92 15361.93,5129.92 15361.93,5117.92 15241.93,4829.92 cw(c15153.68,4875.92) 15175.93,4778.92 14680.93,4778.92 14674.93,4784.92
  lines w20: 8411.4,4173.85 8411.4,5773.85 15911.41,5773.85 ; 8511.4,4773.85 9711.4,4773.85 ; 8511.4,5223.85 9711.4,5223.85 ; 8037.39,4173.85 15911.41,4173.85 15911.41,15473.06 8037.39,15473.06 8037.39,4173.85 ; 8511.4,4273.85 8511.4,5673.85 9711.4,5673.85 9711.4,4273.85 8511.4,4273.85 ; 9811.4,4273.85 14211.41,4273.85 14211.41,5173.85 9811.4,5173.85 9811.4,4273.85 ; 9811.4,5273.85 9811.4,5673.85 14211.41,5673.85 14211.41,5273.85 9811.4,5273.85 ; 14311.4,4273.85 14311.4,5673.85 15811.41,5673.85 15811.41,4273.85 14311.4,4273.85
  text "DATE:" at 8546.94,5380.02 h70
  text "15/05/12" at 8999.69,5380.02 h70
  text "STM32F3-DISCOVERY" at 9907.47,4862.82 h96.46
  text "MB1035A" at 9907.47,4508.49 h96.46
  text "S.M.E.E." at 8648.93,4394.92 h165.35

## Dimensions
10948.93,12694.92 to 13048.93,12194.92 on PERCAGES
13048.93,11494.92 to 13298.15,12826.42 on PERCAGES
13048.93,9094.92 to 12948.93,9094.92 on PERCAGES
11048.93,9094.92 to 10948.93,9094.92 on PERCAGES
10948.93,9094.92 to 13048.93,9094.92 on PERCAGES
10699.72,12826.42 to 10948.93,11494.92 on PERCAGES
10699.72,12826.42 to 13298.15,12826.42 on PERCAGES
10948.93,12694.92 to 10948.93,11494.92 on PERCAGES
13048.93,11494.92 to 13048.93,12194.92 on PERCAGES
10699.72,12826.42 to 10948.93,12694.92 on PERCAGES
13298.15,12826.42 to 13298.15,9007.52 on PERCAGES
